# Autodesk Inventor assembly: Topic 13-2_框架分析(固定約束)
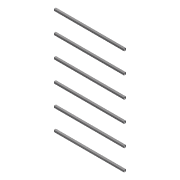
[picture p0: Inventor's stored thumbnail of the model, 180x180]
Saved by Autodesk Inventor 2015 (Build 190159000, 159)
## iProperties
Created: 2020-03
Part Number: Topic 13-2_框架分析(固定約束)
Document SubType Name: Assembly
Designer: 徐冠倫
Mass: 14532.6 g
Surface Area: 12379 cm^2
Volume: 1851.29 cm^3
Density: 7.85 g/cm^3
_SolveAssemblyDoc: Frame Generator Solve Assembly
_Version: 15.0.0
Author: 徐冠倫
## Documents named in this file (3)
- C:\Users\徐冠倫\Desktop\Topic 13-3_框架分析(銷約束)\Topic 13-3_框架分析(銷約束).iam
- C:\Users\徐冠倫\Desktop\Topic 13-3_框架分析(銷約束)\Topic 13-3_框架分析(銷約束).ipt
- C:\Users\徐冠倫\Desktop\Topic 13-3_框架分析(銷約束)\Topic 13-3_框架分析(銷約束)\Frame\Frame0001.iam
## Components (7 placed, 2 different names)
1. Topic 13-3_框架分析(銷約束):1
2. Frame0001:1 [sub-assembly]
3. Frame0001:2 [sub-assembly]
4. Frame0001:3 [sub-assembly]
5. Frame0001:4 [sub-assembly]
6. Frame0001:5 [sub-assembly]
7. Frame0001:6 [sub-assembly]
